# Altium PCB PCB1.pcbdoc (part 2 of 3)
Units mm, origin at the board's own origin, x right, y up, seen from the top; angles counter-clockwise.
Board outline 85.01 x 107.37 mm, 4 copper layers (Top Layer, Inner1, Inner2, Bottom Layer); 103 components, 145 nets, 660 pads, 277 vias.
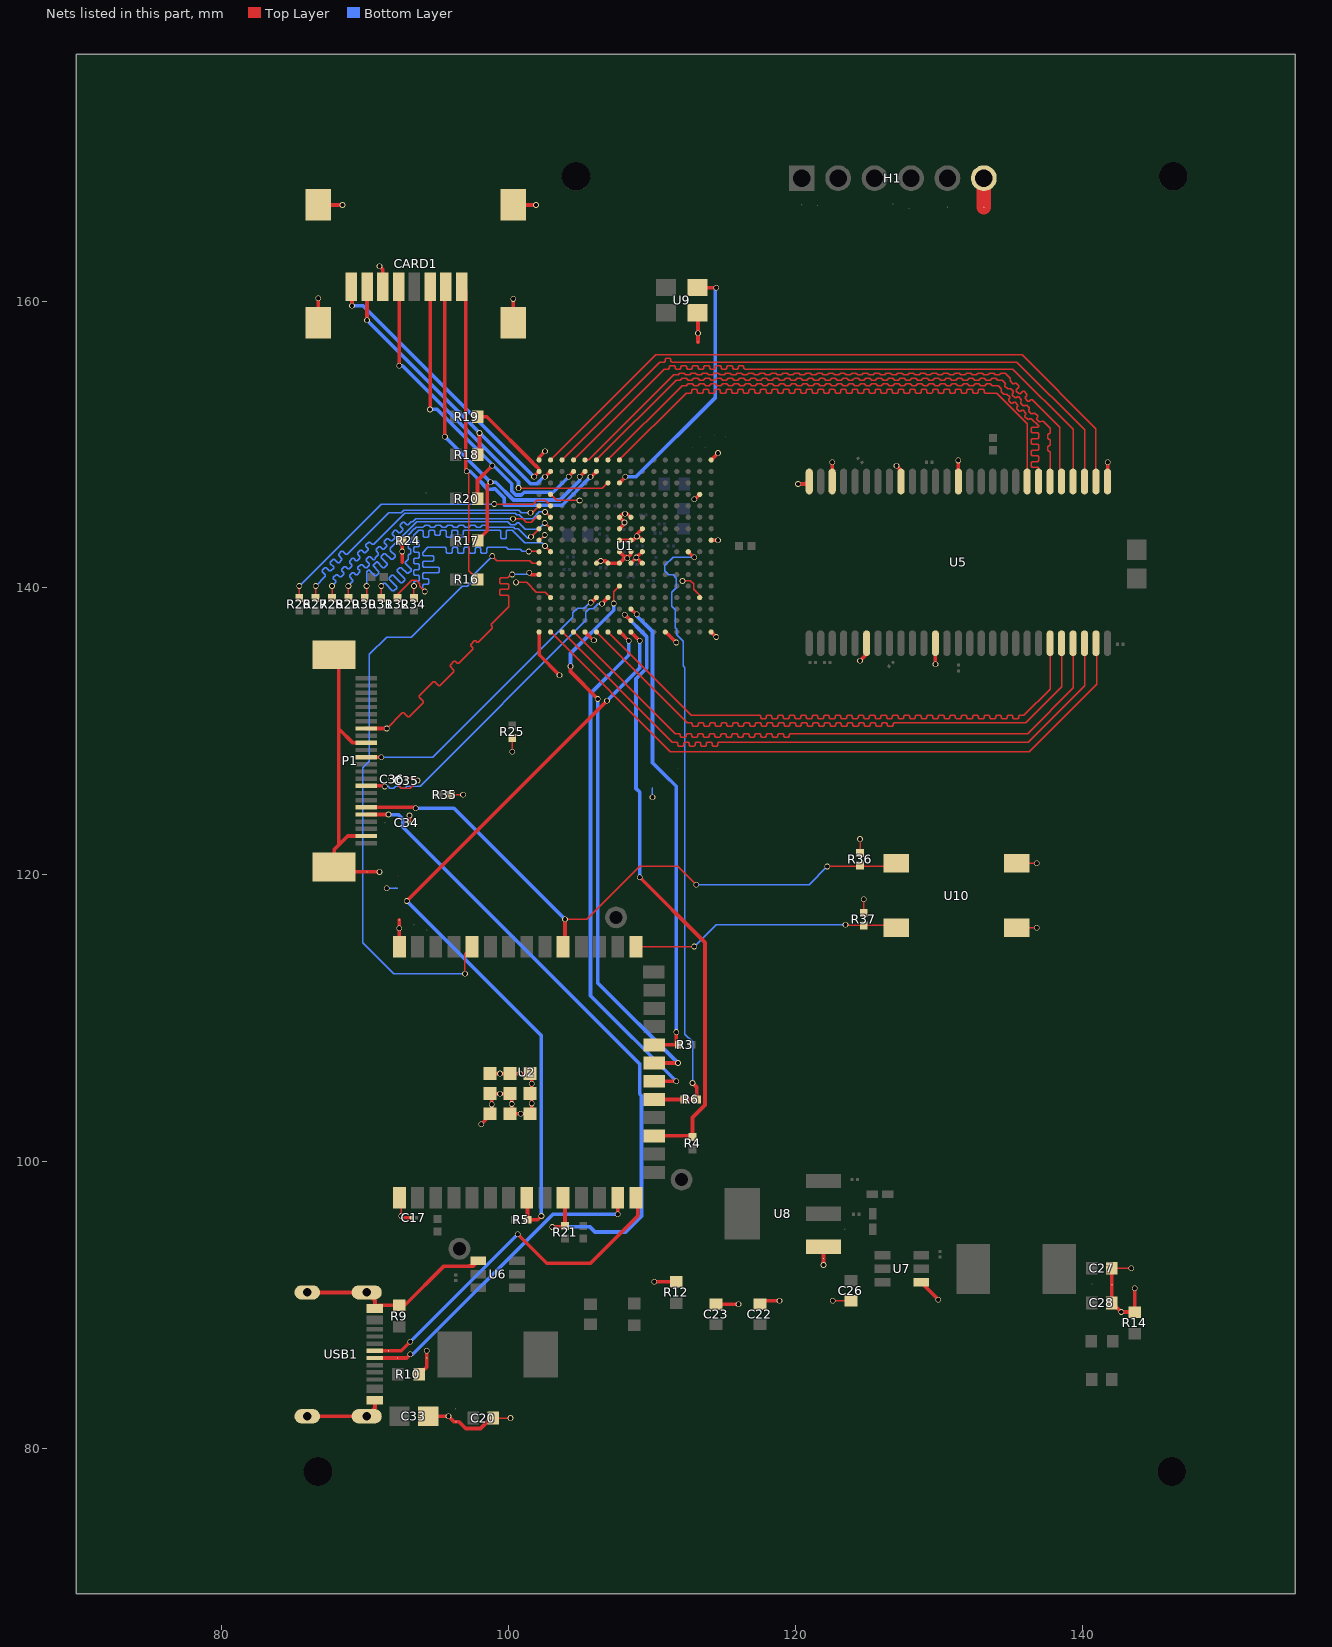
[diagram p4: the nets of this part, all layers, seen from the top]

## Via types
v1: diameter 0.4, hole 0.3, Top Layer to Bottom Layer, 261 vias
v2: diameter 0.61, hole 0.305, Top Layer to Bottom Layer, 16 vias

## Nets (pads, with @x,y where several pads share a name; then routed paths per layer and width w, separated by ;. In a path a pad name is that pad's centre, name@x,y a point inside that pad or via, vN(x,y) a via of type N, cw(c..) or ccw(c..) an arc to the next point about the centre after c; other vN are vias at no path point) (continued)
CCLK: R6.1 R6.2 U1.J14 U2.19 | length 44.3
  Top Layer w0.254: U2.19@110.292,104.318 R6.1@112.267,104.318 R6.2@113.133,104.318 113.133,105.155 v1(112.827,105.461) ; U1.J14@112.528,142.526 112.911,142.143 v1(112.954,142.143)
  Bottom Layer w0.1: v1(112.827,105.461) 112.827,108.34 112.296,108.871 112.296,134.44 112.171,134.565 112.171,136.277 111.714,136.734 111.714,137.124 111.615,137.223 111.615,138.479 111.386,138.708 111.386,139.707 111.705,140.026 111.705,140.68 111.47,140.915 111.184,140.915 110.899,141.199 110.899,141.567 111.475,142.143 v1(112.954,142.143)
CRYSTAL: U1.C8 U9.3 | length 18.2
  Top Layer w0.254: U1.C8@107.728,147.326 108.128,147.726 v1(108.128,147.752) ; U9.3@113.165,160.946 v1(114.478,160.946)
  Bottom Layer w0.254: v1(108.128,147.752) 108.89,147.752 114.425,153.287 114.425,160.893 v1(114.478,160.946)
D0: R26.1 U1.E2 | length 21
  Top Layer w0.1: R26.1@85.395,139.295 v1(85.395,140.132) ; v1@98.984,145.847 101.709,145.847 101.97,146.108 102.546,146.108 U1.E2@102.928,145.726
  Bottom Layer w0.1: v1(85.395,140.132) 91.11,145.847 v1(98.994,145.847)
D1: R27.1 U1.E1 | length 21.1
  Top Layer w0.1: R27.1@86.538,139.295 v1(86.538,140.132) ; v1(101.524,145.241) 101.643,145.241 U1.E1@102.128,145.726
  Bottom Layer w0.1: v1(86.538,140.132) 87.223,140.817 87.223,140.917 87.006,141.135 87.006,141.235 87.188,141.417 87.288,141.417 87.506,141.2 87.606,141.2 87.789,141.383 87.789,141.483 87.571,141.7 87.571,141.8 87.754,141.983 87.854,141.983 88.072,141.766 88.172,141.766 88.354,141.948 88.354,142.048 88.137,142.266 88.137,142.366 88.32,142.549 88.42,142.549 88.637,142.331 88.737,142.331 91.647,145.241 92.507,145.241 92.685,145.419 100.717,145.419 100.895,145.241 v1(101.524,145.241)
D2: R28.1 U1.F2 | length 21.5
  Top Layer w0.1: R28.1@87.681,139.295 v1(87.681,140.132) ; v1(102.537,145.296) 102.558,145.296 U1.F2@102.928,144.926
  Bottom Layer w0.1: v1(87.681,140.132) 87.935,140.386 87.935,140.486 87.781,140.64 87.781,140.74 87.964,140.923 88.064,140.923 88.218,140.769 88.318,140.769 88.501,140.952 88.501,141.052 88.347,141.206 88.347,141.306 88.53,141.489 88.63,141.489 88.784,141.335 88.884,141.335 89.066,141.517 89.066,141.617 88.912,141.771 88.912,141.871 89.095,142.054 89.195,142.054 89.349,141.9 89.449,141.9 89.632,142.083 89.632,142.183 89.478,142.337 89.478,142.437 89.661,142.62 89.761,142.62 89.915,142.466 90.015,142.466 90.198,142.649 90.198,142.749 90.044,142.903 90.044,143.003 90.227,143.186 90.327,143.186 90.481,143.032 90.581,143.032 92.768,145.219 100.465,145.219 100.575,145.11 100.743,145.11 101.014,144.839 101.691,144.839 102.147,145.296 v1(102.537,145.296)
D3: R29.1 U1.F1 | length 20.7
  Top Layer w0.1: R29.1@88.824,139.295 v1(88.824,140.132) ; v1(100.299,144.817) 100.998,144.817 101.23,144.585 101.564,144.585 101.922,144.943 102.111,144.943 U1.F1@102.128,144.926
  Bottom Layer w0.1: v1(88.824,140.132) 89.143,140.451 89.143,140.551 88.926,140.769 88.926,140.869 89.109,141.052 89.209,141.052 89.328,140.932 89.428,140.932 89.611,141.115 89.611,141.215 89.491,141.334 89.491,141.434 89.674,141.617 89.774,141.617 89.992,141.4 90.092,141.4 90.275,141.583 90.275,141.683 90.057,141.9 90.057,142 90.24,142.183 90.34,142.183 90.558,141.966 90.658,141.966 90.71,142.018 90.71,142.114 90.922,142.327 90.922,142.427 90.753,142.596 90.753,142.696 90.936,142.879 91.036,142.879 91.205,142.709 91.305,142.709 91.488,142.892 91.488,142.992 91.319,143.162 91.319,143.262 91.501,143.444 91.601,143.444 91.771,143.275 91.871,143.275 92.054,143.458 92.054,143.558 91.884,143.727 91.884,143.827 92.067,144.01 92.167,144.01 92.336,143.841 92.436,143.841 92.619,144.024 92.619,144.124 92.45,144.293 92.45,144.393 92.633,144.576 92.733,144.576 92.902,144.406 93.002,144.406 93.211,144.615 93.307,144.615 93.509,144.817 v1(100.299,144.817)
D4: R30.1 U1.G2 | length 21.3
  Top Layer w0.1: R30.1@89.967,139.295 90.094,139.422 v1(90.094,140.132) ; v1(102.522,144.529) 102.525,144.529 U1.G2@102.928,144.126
  Bottom Layer w0.1: v1(90.094,140.132) 90.094,141.119 90.24,141.265 90.258,141.265 90.67,140.853 90.77,140.853 90.953,141.036 90.953,141.136 90.541,141.548 90.541,141.566 90.806,141.831 90.824,141.831 91.236,141.419 91.336,141.419 91.519,141.602 91.519,141.702 91.107,142.114 91.107,142.214 91.29,142.397 91.39,142.397 91.802,141.985 91.902,141.985 92.084,142.168 92.084,142.268 91.745,142.607 91.745,142.77 92.171,143.196 92.271,143.196 92.489,142.978 92.589,142.978 92.772,143.16 92.772,143.26 92.554,143.479 92.554,143.579 93.592,144.617 99.93,144.617 100.132,144.415 100.465,144.415 100.592,144.542 100.701,144.542 101.153,144.09 102.082,144.09 v1(102.522,144.529)
D5: R31.1 U1.G1 | length 21
  Top Layer w0.1: R31.1@91.11,139.295 v1(91.11,140.132) ; v1(101.558,143.561) 101.563,143.561 U1.G1@102.128,144.126
  Bottom Layer w0.1: v1(91.11,140.132) 91.289,140.311 91.389,140.311 91.898,139.802 91.998,139.802 92.181,139.985 92.181,140.085 91.672,140.594 91.672,140.694 91.854,140.876 91.954,140.876 92.464,140.367 92.564,140.367 92.746,140.55 92.746,140.65 92.237,141.159 92.237,141.259 92.401,141.423 92.501,141.423 92.913,141.011 93.013,141.011 93.196,141.193 93.196,141.293 92.784,141.706 92.784,141.806 92.984,142.006 92.984,142.264 93.055,142.334 93.096,142.334 93.167,142.405 93.167,142.664 93.096,142.734 93.055,142.734 92.984,142.805 92.984,143.064 93.055,143.134 93.096,143.134 93.167,143.205 93.167,143.464 93.096,143.534 93.055,143.534 92.984,143.605 92.984,143.679 93.43,144.125 93.452,144.125 93.542,144.215 94.027,144.215 94.098,144.286 94.098,144.317 94.169,144.388 94.427,144.388 94.498,144.317 94.498,144.286 94.569,144.215 94.827,144.215 94.898,144.286 94.898,144.317 94.969,144.388 95.227,144.388 95.298,144.317 95.298,144.286 95.369,144.215 95.627,144.215 95.698,144.286 95.698,144.317 95.769,144.388 96.027,144.388 96.098,144.317 96.098,144.286 96.169,144.215 96.427,144.215 96.498,144.286 96.498,144.317 96.569,144.388 96.827,144.388 96.898,144.317 96.898,144.286 96.969,144.215 97.227,144.215 97.298,144.286 97.298,144.317 97.369,144.388 97.627,144.388 97.698,144.317 97.698,144.286 97.769,144.215 98.027,144.215 98.098,144.286 98.098,144.317 98.169,144.388 98.427,144.388 98.498,144.317 98.498,144.286 98.569,144.215 100.353,144.215 100.443,144.125 100.672,144.125 101.326,143.471 101.468,143.471 v1(101.558,143.561)
D6: R32.1 U1.J1 | length 20.9
  Top Layer w0.1: R32.1@92.253,139.295 92.253,139.558 93.229,140.534 93.563,140.534 93.798,140.299 93.798,140.111 v1(94.158,139.751) ; v1(101.397,142.545) 102.109,142.545 U1.J1@102.128,142.526
  Bottom Layer w0.1: v1(94.158,139.751) 94.01,139.899 94.01,140.183 94.081,140.254 94.345,140.254 94.416,140.324 94.416,140.583 94.345,140.654 94.081,140.654 94.01,140.724 94.01,140.983 94.081,141.054 95.103,141.054 95.174,141.124 95.174,141.383 95.103,141.454 94.081,141.454 94.01,141.524 94.01,141.783 94.081,141.854 94.722,141.854 94.793,141.924 94.793,142.183 94.722,142.254 94.081,142.254 94.01,142.324 94.01,142.458 94.372,142.82 95.59,142.82 95.661,142.749 95.661,142.489 95.731,142.418 95.99,142.418 96.061,142.489 96.061,142.749 96.131,142.82 96.39,142.82 96.461,142.749 96.461,142.489 96.531,142.418 96.79,142.418 96.861,142.489 96.861,142.749 96.931,142.82 97.19,142.82 97.261,142.749 97.261,142.489 97.331,142.418 97.59,142.418 97.661,142.489 97.661,142.749 97.731,142.82 97.99,142.82 98.061,142.749 98.061,142.489 98.131,142.418 98.39,142.418 98.461,142.489 98.461,142.749 98.531,142.82 99.852,142.82 99.979,142.693 100.802,142.693 100.95,142.545 v1(101.397,142.545)
D7: R34.1 U1.J2 | length 21
  Top Layer w0.1: R34.1@93.396,139.295 v1(93.396,140.132) ; v1(102.54,142.926) 102.54,142.914 U1.J2@102.928,142.526
  Bottom Layer w0.1: v1(93.396,140.132) 93.396,140.406 93.467,140.477 93.71,140.477 93.781,140.548 93.781,140.806 93.71,140.877 93.467,140.877 93.396,140.948 93.396,141.206 93.467,141.277 93.71,141.277 93.781,141.348 93.781,141.606 93.71,141.677 93.467,141.677 93.396,141.748 93.396,142.006 93.467,142.077 93.71,142.077 93.781,142.148 93.781,142.406 93.71,142.477 93.467,142.477 93.396,142.548 93.396,142.806 93.467,142.877 93.71,142.877 93.781,142.948 93.781,143.206 93.71,143.277 93.467,143.277 93.396,143.348 93.396,143.688 93.723,144.015 93.972,144.015 94.042,143.944 94.042,143.606 94.113,143.535 94.372,143.535 94.442,143.606 94.442,143.944 94.513,144.015 94.772,144.015 94.842,143.944 94.842,143.747 94.913,143.677 95.172,143.677 95.242,143.747 95.242,143.944 95.313,144.015 95.572,144.015 95.642,143.944 95.642,143.606 95.713,143.535 95.972,143.535 96.042,143.606 96.042,143.944 96.113,144.015 96.372,144.015 96.442,143.944 96.442,143.606 96.513,143.535 96.772,143.535 96.842,143.606 96.842,143.944 96.913,144.015 99.367,144.015 99.437,143.944 99.437,143.505 99.508,143.434 99.767,143.434 99.837,143.505 99.837,143.944 99.908,144.015 100.271,144.015 101.127,143.159 102.307,143.159 v1(102.54,142.926)
DIN: U1.T8 U2.20 | length 36.6
  Top Layer w0.254: U1.T8@107.728,136.926 107.778,136.926 v1(108.382,136.322) ; U2.20@110.292,105.588 v1(111.684,105.588)
  Bottom Layer w0.254: v1(108.382,136.322) 108.382,135.306 105.715,132.639 105.715,111.557 v1(111.684,105.588)
DN: pad.55@92.253,86.284 U2.13 USB1.A7 | length 22.3
  Top Layer w0.254: USB1.A7@90.678,86.288 91.975,86.288 92.892,86.288 v1(93.142,86.538) ; v1(107.62,96.317) 107.62,97.351 U2.13@107.742,97.473
  Bottom Layer w0.254: v1(93.142,86.538) 93.311,86.538 103.09,96.317 v1(107.62,96.317)
DONE: pad.55@110.865,126.981 R3.2 U1.P9 U2.22 | length 33.4
  Top Layer w0.254: U1.P9@108.528,138.526 108.898,138.156 v1(108.946,138.156) ; U2.22@110.292,108.128 R3.2@111.886,108.128 111.684,108.33 v1(111.684,109.017)
  Bottom Layer w0.254: v1(108.946,138.156) 108.946,138.044 110.033,136.957 110.033,127.813 pad.55@110.865,126.981 111.684,126.162 v1(111.684,109.017)
DOUT: U1.M8 U2.21 | length 39.3
  Top Layer w0.1: v1(107.328,138.911) 107.328,139.726 U1.M8@107.728,140.126
  Top Layer w0.254: v1(104.318,134.544) 104.318,134.163 v1(106.223,132.258) ; U2.21@110.292,106.858 v1(111.811,106.858)
  Bottom Layer w0.254: v1(104.318,134.544) 104.318,135.433 107.328,138.443 v1(107.328,138.911) ; v1(106.223,132.258) 106.223,112.446 v1(111.811,106.858)
DP: pad.55@91.618,86.792 U2.14 USB1.A6 | length 25.2
  Top Layer w0.254: USB1.A6@90.678,86.788 91.93,86.788 92.503,86.788 v1(93.142,87.427) ; v1(100.635,94.92) 102.667,92.888 105.715,92.888 109.012,96.185 U2.14@109.012,97.473
  Bottom Layer w0.254: v1(93.142,87.427) v1(100.635,94.92)
GND: C17.1 C20.1 C22.1 C23.1 C26.1 C27.1 C28.1 C33.1 C34.2 C35.2 C36.2 CARD1.6 CARD1.9 CARD1.10 CARD1.11 CARD1.12 H1.6 P1.2 P1.15 P1.25 P1.26 pad.55@90.131,120.193 pad.55@92.126,119.05 pad.55@92.375,116.832 pad.55@94.285,86.284 pad.55@96.317,81.839 pad.55@110.033,126.035 pad.55@113.208,157.15 pad.55@121.965,93.234 pad.55@133.147,166.548 pad.55@142.081,91.393 R9.1 R10.1 R12.1 R14.1 R24.1 R25.1 R35.2 R36.2 R37.2 U1.A1 U1.A16 U1.D2 U1.D15 U1.F8 U1.F9 U1.G8 U1.G10 U1.H1 U1.H8 U1.H9 U1.H10 U1.H16 U1.J8 U1.J9 U1.J10 U1.K6 U1.K7 U1.K8 U1.K9 U1.K10 U1.N2 U1.N15 U1.T1 U1.T5 U1.T12 U1.T16 U2.1 U2.40 U2.41 U5.6 U5.12 U5.28 U5.41 U5.46 U5.52 U5.54 U6.4 U7.4 U8.1 U9.2 U10.2 U10.4 USB1.1 USB1.2 USB1.3 USB1.4 USB1.A1B12 USB1.B1A12 | length 143
  Top Layer w0.1: C36.2@92.067,126.67 92.067,126.475 92.501,126.041 93.148,126.041 93.65,126.543 v1(93.65,126.564) 93.476,126.738 C35.2@92.888,126.738 ; U2.1@92.375,97.473 92.502,97.346 v1(92.502,96.19) ; R35.2@95.974,125.576 v1(96.825,125.576) ; C20.1@98.922,82.093 v1(100.127,82.093) ; v1(100.254,128.575) R25.1@100.254,129.539 ; v1(100.508,140.386) 101.27,140.386 101.942,139.714 102.54,139.714 U1.N2@102.928,139.326 ; 102.286,143.434 102.528,143.676 v1(102.528,143.688) ; U1.D2@102.928,146.526 103.353,146.101 103.563,146.101 103.57,146.108 104.686,146.108 104.693,146.101 v1@104.953,146.101 ; v1(112.128,140.478) 112.267,140.478 112.297,140.508 112.686,140.508 112.91,140.284 112.91,139.895 113.328,139.477 U1.N15@113.328,139.326 ; v1(122.606,90.283) C26.1@123.876,90.283 ; R36.2@124.511,121.515 v1(124.511,122.479) ; R37.2@124.765,117.324 v1(124.765,118.288) ; U10.4@135.442,116.292 v1(136.83,116.292) ; U10.2@135.442,120.792 v1(136.83,120.792) ; C27.1@142.081,92.546 v1(143.434,92.546)
  Top Layer w0.254: USB1.4@85.954,82.218 USB1.2@90.103,82.218 90.678,82.793 USB1.B1A12@90.678,83.338 ; USB1.3@85.954,90.858 USB1.1@90.103,90.858 90.678,90.283 USB1.A1B12@90.678,89.738 90.899,89.958 R9.1@92.38,89.958 92.761,89.958 95.498,92.695 97.212,92.695 97.222,92.705 97.517,92.705 U6.4@97.888,93.076 ; CARD1.10@86.723,158.511 v1(86.723,160.202) ; CARD1.9@86.723,166.711 v1(88.408,166.711) ; P1.25@87.819,135.341 88.153,135.007 88.153,130.184 ; P1.2@90.08,122.695 88.786,122.695 88.153,122.062 ; P1.15@90.081,129.191 89.147,129.191 88.153,130.184 ; v1(90.996,162.438) 91.223,162.211 CARD1.6@91.223,161.011 ; v1(91.001,120.193) pad.55@90.131,120.193 88.172,120.193 P1.26@87.826,120.539 87.826,121.735 88.153,122.062 ; pad.55@92.375,116.832 v1(92.375,116.26) 92.375,115.1 U2.40@92.502,114.973 ; v1(92.502,96.19) 92.629,96.063 C17.1@93.201,96.063 ; 92.582,141.783 v1(92.582,142.539) R24.1@92.582,143.307 ; C34.2@93.083,123.622 v1(93.083,124.13) ; R10.1@93.768,85.141 94.285,85.658 pad.55@94.285,86.284 v1(94.285,86.792) ; C33.1@94.396,82.22 v1(95.809,82.22) 96.19,81.839 96.531,81.839 97.006,81.364 98.038,81.364 98.767,82.093 C20.1@98.922,82.093 ; v1(98.096,102.597) 98.822,103.323 v1(98.822,103.976) 98.822,104.723 v1(99.398,104.723) 100.222,104.723 v1(100.222,104.001) 100.222,103.323 v1(100.842,103.323) 101.622,103.323 v1(101.622,104.045) v1(101.622,105.407) 101.622,106.123 v1(100.773,106.123) v1(99.398,106.123) U2.41@98.822,106.123 ; CARD1.11@100.323,158.511 v1(100.323,160.16) ; CARD1.12@100.323,166.711 v1(101.905,166.711) ; U1.T1@102.128,136.926 102.128,135.337 v1(103.556,133.909) ; U1.A1@102.128,148.926 102.128,149.118 v1(102.54,149.53) ; U1.T5@105.328,136.926 105.911,136.343 v1(105.948,136.343) ; U1.K6@106.128,141.726 106.282,141.881 v1(106.427,141.881) 106.774,141.881 U1.K7@106.928,141.726 U1.K8@107.728,141.726 v1@108.19,142.188 ; U1.J8@107.728,142.526 108.066,142.188 v1@108.19,142.188 ; U1.H8@107.728,143.326 U1.H9@108.528,143.326 108.679,143.326 v1(108.947,143.594) ; U1.G8@107.728,144.126 108.08,144.478 v1(108.08,144.557) 108.08,144.574 U1.F8@107.728,144.926 107.982,145.18 v1(108.119,145.18) 108.274,145.18 U1.F9@108.528,144.926 ; U1.K9@108.528,141.726 108.907,142.105 v1(108.907,142.118) ; U1.J9@108.528,142.526 108.528,142.329 v1(108.269,142.069) 108.269,142.109 v1@108.19,142.188 ; U1.K10@109.172,141.754 109.172,141.852 v1(108.907,142.118) ; U1.J10@109.328,142.526 109.315,142.526 v1(108.907,142.118) ; U1.H10@109.328,143.326 109.06,143.594 v1(108.947,143.594) ; U1.G10@109.328,144.126 108.947,143.745 v1(108.947,143.594) ; v1(110.16,91.609) R12.1@111.684,91.609 ; U1.T12@110.928,136.926 110.953,136.926 v1(111.685,136.194) ; v1@112.954,146.228 113.03,146.228 U1.D15@113.328,146.526 ; U9.2@113.165,159.196 113.208,159.153 v1(113.208,157.755) pad.55@113.208,157.15 ; U1.T16@114.128,136.926 v1(114.478,136.576) ; U1.H16@114.128,143.326 v1(114.605,143.328) ; U1.A16@114.128,148.926 v1(114.605,149.403) ; C23.1@114.478,90.032 v1(116.032,90.032) ; C22.1@117.526,90.032 117.777,90.283 v1(118.897,90.283) ; v1(120.193,147.244) 120.661,147.244 U5.54@120.969,147.552 ; v1(121.965,92.771) pad.55@121.965,93.234 U8.1@121.965,94.046 ; U5.52@122.569,147.552 v1(122.569,148.768) ; v1(124.511,134.925) 124.969,135.383 U5.6@124.969,136.141 ; v1(127.051,148.514) 127.369,148.196 U5.46@127.369,147.425 ; U7.4@128.782,91.557 129.972,90.367 v1(129.972,90.348) ; v1(129.769,134.671) U5.12@129.769,136.141 ; U5.41@131.369,147.552 v1(131.369,148.895) ; U5.28@141.769,147.425 141.783,147.439 v1(141.783,148.768) ; C27.1@142.081,92.546 pad.55@142.081,91.393 C28.1@142.081,90.133 v1(142.725,89.489) R14.1@143.667,89.489 v1(143.667,91.149) ; 88.153,122.062 88.153,130.184
  Top Layer w1: pad.55@133.147,166.548 H1.6@133.147,168.58
  Bottom Layer w0.1: v1(91.491,119.05) 92.253,119.05 ; v1(110.033,125.4) pad.55@110.033,126.035
  other v1: 104.952,146.102 112.954,146.181
HREF: P1.9 U1.N7 | length 22.9
  Top Layer w0.254: P1.9@90.08,126.194 91.323,126.194 v1(91.365,126.152) ; v1@106.477,138.862 106.477,138.875 U1.N7@106.928,139.326
  Bottom Layer w0.1: v1(91.365,126.152) 91.594,126.152 91.712,126.035 91.985,126.035 92.112,126.162 92.385,126.162 92.512,126.035 92.785,126.035 92.912,126.162 93.826,126.162 105.394,137.73 105.394,138.313 105.629,138.548 105.909,138.548 106.257,138.896 v1(106.511,138.896)
INITN: pad.55@93.673,117.376 R5.1 U1.T9 U2.8 | length 54.3
  Top Layer w0.254: v1(92.888,118.161) v1(106.858,132.131) ; U2.8@101.392,97.473 101.322,97.403 R5.1@101.322,95.936 102.032,95.936 v1(102.286,96.19) ; U1.T9@108.528,136.926 109.132,136.322 v1(109.144,136.322)
  Bottom Layer w0.254: v1(92.888,118.161) pad.55@93.673,117.376 102.286,108.763 v1(102.286,96.19) ; v1(106.858,132.131) 109.144,134.417 v1(109.144,136.322)
M_CLK: CARD1.5 U1.C7 | length 24
  Top Layer w0.1: v1(100.69,146.962) 100.707,146.944 106.546,146.944 U1.C7@106.928,147.326
  Top Layer w0.254: CARD1.5@92.323,161.011 92.38,160.954 v1(92.38,155.499)
  Bottom Layer w0.254: v1(92.38,155.499) 92.592,155.499 100.69,147.401 v1(100.69,146.962)
M_CMD: CARD1.3 R20.1 U1.B4 | length 24.7
  Top Layer w0.254: v1(94.523,152.451) CARD1.3@94.523,161.011 ; R20.1@97.832,146.228 97.832,147.489 v1(98.857,148.514) ; v1(104.191,147.752) 104.191,147.789 U1.B4@104.528,148.126
  Bottom Layer w0.254: v1(94.523,152.451) 95.031,152.451 100.211,147.271 100.211,146.763 100.491,146.483 100.888,146.483 101.087,146.682 103.121,146.682 v1(104.191,147.752)
M_D0: CARD1.7 R18.1 U1.B2 | length 21.8
  Top Layer w0.254: v1(90.123,158.674) CARD1.7@90.123,161.011 ; R18.1@97.832,149.276 97.968,149.412 v1(97.968,150.8) ; v1(102.54,147.752) 102.554,147.752 U1.B2@102.928,148.126
  Bottom Layer w0.254: v1(90.123,158.674) 101.524,147.273 101.976,147.273 102.455,147.752 v1(102.54,147.752)
M_D1: CARD1.8 R19.1 U1.B1 | length 25.5
  Top Layer w0.254: CARD1.8@89.023,161.011 89.078,160.956 v1(89.078,159.69) ; R19.1@97.832,151.943 98.467,151.943 101.669,148.741 101.669,148.736 101.938,148.467 101.943,148.467 102.096,148.315 U1.B1@102.096,148.093 ; v1(101.778,147.752) 101.778,147.776 U1.B1@102.096,148.093 ; U1.B1@102.128,148.126 U1.B1@102.096,148.093
  Bottom Layer w0.254: v1(89.078,159.69) 89.84,159.69 v1(101.778,147.752)
M_D2: CARD1.1 R16.1 U1.B6 | length 32.2
  Top Layer w0.1: v1(97.079,148.133) 97.227,147.985 97.227,141.19 R16.1@97.828,140.589
  Top Layer w0.254: CARD1.1@96.723,161.011 97.008,160.726 97.008,148.204 v1(97.079,148.133) ; v1(105.715,147.752) 105.754,147.752 U1.B6@106.128,148.126
  Bottom Layer w0.254: v1(97.079,148.133) 97.333,148.133 98.251,147.215 98.251,147.173 98.532,146.892 98.928,146.892 98.942,146.906 99.067,146.906 99.704,146.269 99.704,145.775 103.738,145.775 v1(105.715,147.752)
M_D3: CARD1.2 R17.1 U1.B5 | length 27.5
  Top Layer w0.254: v1(95.555,150.546) 95.555,160.943 CARD1.2@95.623,161.011 ; R17.1@97.832,143.307 98.515,143.989 98.515,147.156 v1(98.73,147.371) ; v1(104.953,147.752) U1.B5@105.328,148.126
  Bottom Layer w0.254: v1(95.555,150.546) v1(98.73,147.371) 99.102,147.371 100.345,146.129 103.591,146.129 104.953,147.491 v1(104.953,147.752)
MCLK: P1.13 U1.N6 | length 20.8
  Top Layer w0.254: P1.13@90.08,128.194 v1(91.11,128.194) ; v1@105.715,138.989 105.791,138.989 U1.N6@106.128,139.326
  Bottom Layer w0.1: v1(91.11,128.194) 94.717,128.194 104.482,137.96 104.482,138.264 104.805,138.587 105.276,138.587 105.664,138.975 v1(105.729,138.975)
PCLK: P1.17 U1.L1 | length 22.6
  Top Layer w0.1: v1(91.491,130.194) 92.586,131.29 92.686,131.29 92.956,131.02 93.056,131.02 94.034,131.997 94.034,132.097 93.764,132.367 93.764,132.467 94.742,133.445 94.842,133.445 95.112,133.175 95.212,133.175 96.189,134.153 96.189,134.253 95.919,134.522 95.919,134.622 96.17,134.874 96.27,134.874 96.409,134.736 96.509,134.736 97.486,135.713 97.486,135.813 97.348,135.951 97.348,136.051 97.601,136.304 97.701,136.304 97.781,136.224 97.881,136.224 98.858,137.202 98.858,137.302 98.779,137.382 98.779,137.482 100,138.703 100,139.422 99.929,139.492 99.441,139.492 99.37,139.563 99.37,139.822 99.441,139.892 99.929,139.892 100,139.963 100,140.222 99.929,140.292 99.441,140.292 99.37,140.363 99.37,140.622 99.441,140.692 99.929,140.692 100.175,140.938 v1(100.254,140.938)
  Top Layer w0.254: P1.17@90.079,130.194 v1(91.491,130.194) ; v1(101.442,141.066) 101.581,140.926 U1.L1@102.128,140.926
  Bottom Layer w0.1: v1(100.254,140.938) 101.314,140.938 v1(101.442,141.066)
PROGRAM: R37.1 U2.27 U10.3 | length 18.9
  Top Layer w0.1: U2.27@108.885,114.973 112.941,114.973 v1(112.954,114.986) ; v1(123.495,116.51) 123.547,116.458 R37.1@124.765,116.458 126.876,116.458 U10.3@127.042,116.292
  Bottom Layer w0.1: v1(112.954,114.986) 114.478,116.51 v1(123.495,116.51)
PROGRAMN: pad.55@108.89,126.014 R4.2 U1.R9 U2.17 | length 42.9
  Top Layer w0.254: v1(108.091,138.137) 108.117,138.137 U1.R9@108.528,137.726 ; v1(109.144,119.812) 113.695,115.261 113.695,103.932 112.827,103.065 R4.2@112.827,101.703 112.752,101.778 U2.17@110.292,101.778
  Bottom Layer w0.254: v1(108.091,138.137) 109.623,136.605 109.623,134.395 108.89,133.662 pad.55@108.89,126.014 109.144,125.76 v1(109.144,119.812)
RESET: P1.6 pad.55@99.749,121.074 R36.1 U2.31 U10.1 | length 44.8
  Top Layer w0.1: v1(103.932,116.891) 105.461,116.891 109.144,120.574 111.811,120.574 v1(113.081,119.304) ; v1(122.225,120.574) 126.824,120.574 U10.1@127.042,120.792
  Top Layer w0.254: P1.6@90.08,124.695 93.466,124.695 v1(93.523,124.638) ; U2.31@103.932,114.973 v1(103.932,116.891)
  Bottom Layer w0.1: v1(113.081,119.304) 120.955,119.304 v1(122.225,120.574)
  Bottom Layer w0.254: v1(93.523,124.638) 96.185,124.638 pad.55@99.749,121.074 v1(103.932,116.891)
RX: U1.K1 U2.36 | length 45.5
  Top Layer w0.1: v1(96.952,113.081) 96.952,114.47 U2.36@97.455,114.973 ; v1(98.858,142.219) 99.186,141.891 101.485,141.891 101.65,141.726 U1.K1@102.128,141.726
  Bottom Layer w0.1: v1(96.952,113.081) 91.999,113.081 89.84,115.24 89.84,127.468 90.28,127.908 90.28,135.365 91.491,136.576 93.215,136.576 96.75,140.111 97.119,140.111 97.354,140.346 97.354,140.715 v1(98.858,142.219)
SCL: P1.5 R21.1 U2.10 | length 46.9
  Top Layer w0.254: P1.5@90.08,124.194 v1(91.618,124.194) ; v1(103.048,95.428) 103.885,95.428 R21.1@103.937,95.48 ; U2.10@103.932,97.473 103.937,97.468 R21.1@103.937,95.555
  Bottom Layer w0.254: v1(91.618,124.194) 91.745,124.194 91.766,124.174 92.324,124.174 92.605,123.893 92.605,123.334 109.144,106.795 109.144,104.706 109.271,104.579 109.271,96.19 108.157,95.076 106.025,95.076 105.673,95.428 v1(103.048,95.428)
SD_A0: U1.T6 U5.23 | length 45.3
  Top Layer w0.1: U1.T6@106.128,136.926 112.447,130.607 112.747,130.607 112.818,130.536 112.818,130.424 112.888,130.353 113.147,130.353 113.218,130.424 113.218,130.536 113.288,130.607 113.547,130.607 113.618,130.536 113.618,130.424 113.688,130.353 113.947,130.353 114.018,130.424 114.018,130.536 114.088,130.607 114.347,130.607 114.418,130.536 114.418,130.424 114.488,130.353 114.747,130.353 114.818,130.424 114.818,130.536 114.888,130.607 115.147,130.607 115.218,130.536 115.218,130.424 115.288,130.353 115.547,130.353 115.618,130.424 115.618,130.536 115.688,130.607 115.947,130.607 116.018,130.536 116.018,130.424 116.088,130.353 116.347,130.353 116.418,130.424 116.418,130.536 116.488,130.607 116.747,130.607 116.818,130.536 116.818,130.424 116.888,130.353 117.147,130.353 117.218,130.424 117.218,130.536 117.288,130.607 117.547,130.607 117.618,130.536 117.618,130.424 117.688,130.353 117.947,130.353 118.018,130.424 118.018,130.536 118.088,130.607 118.347,130.607 118.418,130.536 118.418,130.424 118.488,130.353 118.747,130.353 118.818,130.424 118.818,130.536 118.888,130.607 119.147,130.607 119.218,130.536 119.218,130.424 119.288,130.353 119.547,130.353 119.618,130.424 119.618,130.536 119.688,130.607 119.947,130.607 120.018,130.536 120.018,130.424 120.088,130.353 120.347,130.353 120.418,130.424 120.418,130.536 120.488,130.607 120.747,130.607 120.818,130.536 120.818,130.424 120.888,130.353 121.147,130.353 121.218,130.424 121.218,130.536 121.288,130.607 121.547,130.607 121.618,130.536 121.618,130.424 121.688,130.353 121.947,130.353 122.018,130.424 122.018,130.536 122.088,130.607 122.347,130.607 122.418,130.536 122.418,130.424 122.488,130.353 122.747,130.353 122.818,130.424 122.818,130.536 122.888,130.607 123.147,130.607 123.218,130.536 123.218,130.424 123.288,130.353 123.547,130.353 123.618,130.424 123.618,130.536 123.688,130.607 123.947,130.607 124.018,130.536 124.018,130.424 124.088,130.353 124.347,130.353 124.418,130.424 124.418,130.536 124.488,130.607 124.747,130.607 124.818,130.536 124.818,130.424 124.888,130.353 125.147,130.353 125.218,130.424 125.218,130.536 125.288,130.607 125.547,130.607 125.618,130.536 125.618,130.424 125.688,130.353 125.947,130.353 126.018,130.424 126.018,130.536 126.088,130.607 126.347,130.607 126.418,130.536 126.418,130.424 126.488,130.353 126.747,130.353 126.818,130.424 126.818,130.536 126.888,130.607 136.068,130.607 138.569,133.108 U5.23@138.569,136.141
SD_A1: U1.T4 U5.24 | length 45.6
  Top Layer w0.1: U1.T4@104.528,136.926 111.609,129.845 111.909,129.845 111.98,129.774 111.98,129.662 112.05,129.591 112.309,129.591 112.38,129.662 112.38,129.774 112.45,129.845 112.709,129.845 112.78,129.774 112.78,129.662 112.85,129.591 113.109,129.591 113.18,129.662 113.18,129.774 113.25,129.845 113.509,129.845 113.58,129.774 113.58,129.662 113.65,129.591 113.909,129.591 113.98,129.662 113.98,129.774 114.05,129.845 114.309,129.845 114.38,129.774 114.38,129.662 114.45,129.591 114.709,129.591 114.78,129.662 114.78,129.774 114.85,129.845 115.109,129.845 115.18,129.774 115.18,129.662 115.25,129.591 115.509,129.591 115.58,129.662 115.58,129.774 115.65,129.845 115.909,129.845 115.98,129.774 115.98,129.662 116.05,129.591 116.309,129.591 116.38,129.662 116.38,129.774 116.45,129.845 116.709,129.845 116.78,129.774 116.78,129.662 116.85,129.591 117.109,129.591 117.18,129.662 117.18,129.774 117.25,129.845 117.509,129.845 117.58,129.774 117.58,129.662 117.65,129.591 117.909,129.591 117.98,129.662 117.98,129.774 118.05,129.845 118.309,129.845 118.38,129.774 118.38,129.662 118.45,129.591 118.709,129.591 118.78,129.662 118.78,129.774 118.85,129.845 119.109,129.845 119.18,129.774 119.18,129.662 119.25,129.591 119.509,129.591 119.58,129.662 119.58,129.774 119.65,129.845 136.195,129.845 139.37,133.02 U5.24@139.37,136.14
SD_A2: U1.T3 U5.25 | length 45.9
  Top Layer w0.1: U1.T3@103.728,136.926 111.407,129.247 111.73,129.247 111.801,129.176 111.801,129.027 111.871,128.956 112.13,128.956 112.201,129.027 112.201,129.176 112.271,129.247 112.53,129.247 112.601,129.176 112.601,129.027 112.671,128.956 112.93,128.956 113.001,129.027 113.001,129.176 113.071,129.247 113.33,129.247 113.401,129.176 113.401,129.027 113.471,128.956 113.73,128.956 113.801,129.027 113.801,129.176 113.871,129.247 114.13,129.247 114.201,129.176 114.201,129.027 114.271,128.956 114.53,128.956 114.601,129.027 114.601,129.176 114.671,129.247 136.232,129.247 140.169,133.184 U5.25@140.169,136.141
SD_A3: U1.T2 U5.26 | length 46.4
  Top Layer w0.1: U1.T2@102.928,136.926 111.279,128.575 136.322,128.575 141.021,133.274 141.021,136.089 U5.26@140.969,136.141
SD_A4: U1.A2 U5.29 | length 46.9
  Top Layer w0.1: U1.A2@102.928,148.926 110.263,156.261 135.814,156.261 140.969,151.106 U5.29@140.969,147.425
SD_A5: U1.A3 U5.30 | length 45.2
  Top Layer w0.1: U1.A3@103.728,148.926 110.555,155.753 110.855,155.753 110.926,155.824 110.926,155.936 110.996,156.007 111.255,156.007 111.326,155.936 111.326,155.824 111.396,155.753 135.433,155.753 140.169,151.017 U5.30@140.169,147.425
SD_A6: U1.A4 U5.31 | length 45.2
  Top Layer w0.1: U1.A4@104.528,148.926 110.847,155.245 111.147,155.245 111.218,155.316 111.218,155.428 111.288,155.499 111.547,155.499 111.618,155.428 111.618,155.316 111.688,155.245 111.947,155.245 112.018,155.316 112.018,155.428 112.088,155.499 112.347,155.499 112.418,155.428 112.418,155.316 112.488,155.245 112.747,155.245 112.818,155.316 112.818,155.428 112.888,155.499 113.147,155.499 113.218,155.428 113.218,155.316 113.288,155.245 113.547,155.245 113.618,155.316 113.618,155.428 113.688,155.499 113.947,155.499 114.018,155.428 114.018,155.316 114.088,155.245 114.347,155.245 114.418,155.316 114.418,155.428 114.488,155.499 114.747,155.499 114.818,155.428 114.818,155.316 114.888,155.245 115.147,155.245 115.218,155.316 115.218,155.428 115.288,155.499 115.547,155.499 115.618,155.428 115.618,155.316 115.688,155.245 115.947,155.245 116.018,155.316 116.018,155.428 116.088,155.499 116.347,155.499 116.418,155.428 116.418,155.316 116.488,155.245 135.179,155.245 139.369,151.055 U5.31@139.369,147.425
SD_A7: U1.A5 U5.32 | length 45.1
  Top Layer w0.1: U1.A5@105.328,148.926 105.588,148.926 111.526,154.864 111.826,154.864 111.953,154.991 112.226,154.991 112.353,154.864 112.626,154.864 112.753,154.991 113.026,154.991 113.153,154.864 113.426,154.864 113.553,154.991 113.826,154.991 113.953,154.864 114.226,154.864 114.353,154.991 114.626,154.991 114.753,154.864 115.026,154.864 115.153,154.991 115.426,154.991 115.553,154.864 115.826,154.864 115.953,154.991 116.226,154.991 116.353,154.864 116.626,154.864 116.753,154.991 117.026,154.991 117.153,154.864 117.426,154.864 117.553,154.991 117.826,154.991 117.953,154.864 118.226,154.864 118.353,154.991 118.626,154.991 118.753,154.864 119.026,154.864 119.153,154.991 119.426,154.991 119.553,154.864 119.826,154.864 119.953,154.991 120.226,154.991 120.353,154.864 120.626,154.864 120.753,154.991 121.026,154.991 121.153,154.864 121.426,154.864 121.553,154.991 121.826,154.991 121.953,154.864 122.226,154.864 122.353,154.991 122.626,154.991 122.753,154.864 123.026,154.864 123.153,154.991 123.426,154.991 123.553,154.864 123.826,154.864 123.953,154.991 124.226,154.991 124.353,154.864 124.626,154.864 124.753,154.991 125.026,154.991 125.153,154.864 125.426,154.864 125.553,154.991 125.826,154.991 125.953,154.864 126.226,154.864 126.353,154.991 126.626,154.991 126.753,154.864 127.026,154.864 127.153,154.991 127.426,154.991 127.553,154.864 127.826,154.864 127.953,154.991 128.226,154.991 128.353,154.864 128.626,154.864 128.753,154.991 129.026,154.991 129.153,154.864 129.426,154.864 129.553,154.991 129.826,154.991 129.953,154.864 130.226,154.864 130.353,154.991 130.626,154.991 130.753,154.864 131.026,154.864 131.153,154.991 131.426,154.991 131.553,154.864 131.826,154.864 131.953,154.991 132.226,154.991 132.353,154.864 132.626,154.864 132.753,154.991 133.026,154.991 133.153,154.864 133.426,154.864 133.553,154.991 133.826,154.991 133.953,154.864 134.226,154.864 134.353,154.991 134.626,154.991 134.998,154.619 134.998,154.44 135.181,154.257 135.281,154.257 135.293,154.269 135.393,154.269 135.576,154.086 135.576,153.986 135.422,153.832 135.422,153.732 135.604,153.549 135.704,153.549 135.859,153.703 135.959,153.703 136.142,153.52 136.142,153.42 136.036,153.315 136.036,153.215 136.219,153.032 136.319,153.032 136.424,153.138 136.524,153.138 138.442,151.22 138.442,147.552 U5.32@138.569,147.425
SD_A8: U1.A6 U5.33 | length 44.4
  Top Layer w0.1: U1.A6@106.128,148.926 111.685,154.483 111.985,154.483 112.056,154.554 112.056,154.564 112.126,154.635 112.385,154.635 112.456,154.564 112.456,154.554 112.526,154.483 112.785,154.483 112.856,154.554 112.856,154.564 112.926,154.635 113.185,154.635 113.256,154.564 113.256,154.554 113.326,154.483 113.585,154.483 113.656,154.554 113.656,154.564 113.726,154.635 113.985,154.635 114.056,154.564 114.056,154.554 114.126,154.483 114.385,154.483 114.456,154.554 114.456,154.564 114.526,154.635 114.785,154.635 114.856,154.564 114.856,154.554 114.926,154.483 115.185,154.483 115.256,154.554 115.256,154.564 115.326,154.635 115.585,154.635 115.656,154.564 115.656,154.554 115.726,154.483 115.985,154.483 116.056,154.554 116.056,154.564 116.126,154.635 116.385,154.635 116.456,154.564 116.456,154.554 116.526,154.483 116.785,154.483 116.856,154.554 116.856,154.564 116.926,154.635 117.185,154.635 117.256,154.564 117.256,154.554 117.326,154.483 117.585,154.483 117.656,154.554 117.656,154.564 117.726,154.635 117.985,154.635 118.056,154.564 118.056,154.554 118.126,154.483 118.385,154.483 118.456,154.554 118.456,154.564 118.526,154.635 118.785,154.635 118.856,154.564 118.856,154.554 118.926,154.483 119.185,154.483 119.256,154.554 119.256,154.564 119.326,154.635 119.585,154.635 119.656,154.564 119.656,154.554 119.726,154.483 119.985,154.483 120.056,154.554 120.056,154.564 120.126,154.635 120.385,154.635 120.456,154.564 120.456,154.554 120.526,154.483 120.785,154.483 120.856,154.554 120.856,154.564 120.926,154.635 121.185,154.635 121.256,154.564 121.256,154.554 121.326,154.483 121.585,154.483 121.656,154.554 121.656,154.564 121.726,154.635 121.985,154.635 122.056,154.564 122.056,154.554 122.126,154.483 122.385,154.483 122.456,154.554 122.456,154.564 122.526,154.635 122.785,154.635 122.856,154.564 122.856,154.554 122.926,154.483 123.185,154.483 123.256,154.554 123.256,154.564 123.326,154.635 123.585,154.635 123.656,154.564 123.656,154.554 123.726,154.483 123.985,154.483 124.056,154.554 124.056,154.564 124.126,154.635 124.385,154.635 124.456,154.564 124.456,154.554 124.526,154.483 124.785,154.483 124.856,154.554 124.856,154.564 124.926,154.635 125.185,154.635 125.256,154.564 125.256,154.554 125.326,154.483 125.585,154.483 125.656,154.554 125.656,154.564 125.726,154.635 125.985,154.635 126.056,154.564 126.056,154.554 126.126,154.483 126.385,154.483 126.456,154.554 126.456,154.564 126.526,154.635 126.785,154.635 126.856,154.564 126.856,154.554 126.926,154.483 127.185,154.483 127.256,154.554 127.256,154.564 127.326,154.635 127.585,154.635 127.656,154.564 127.656,154.554 127.726,154.483 127.985,154.483 128.056,154.554 128.056,154.564 128.126,154.635 128.385,154.635 128.456,154.564 128.456,154.554 128.526,154.483 128.785,154.483 128.856,154.554 128.856,154.564 128.926,154.635 129.185,154.635 129.256,154.564 129.256,154.554 129.326,154.483 129.585,154.483 129.656,154.554 129.656,154.564 129.726,154.635 129.985,154.635 130.056,154.564 130.056,154.554 130.126,154.483 130.385,154.483 130.456,154.554 130.456,154.564 130.526,154.635 130.785,154.635 130.856,154.564 130.856,154.554 130.926,154.483 131.185,154.483 131.256,154.554 131.256,154.564 131.326,154.635 131.585,154.635 131.656,154.564 131.656,154.554 131.726,154.483 131.985,154.483 132.056,154.554 132.056,154.564 132.126,154.635 132.385,154.635 132.456,154.564 132.456,154.554 132.526,154.483 132.785,154.483 132.856,154.554 132.856,154.564 132.926,154.635 133.185,154.635 133.256,154.564 133.256,154.554 133.326,154.483 133.585,154.483 133.656,154.554 133.656,154.564 133.726,154.635 133.985,154.635 134.056,154.564 134.056,154.554 134.126,154.483 134.417,154.483 134.629,154.271 134.629,154.171 134.617,154.159 134.617,154.059 134.8,153.876 134.9,153.876 134.912,153.888 135.012,153.888 135.195,153.705 135.195,153.605 135.139,153.55 135.139,153.45 135.322,153.267 135.422,153.267 135.478,153.322 135.578,153.322 135.761,153.139 135.761,153.039 135.705,152.984 135.705,152.884 135.888,152.701 135.988,152.701 136.043,152.757 136.143,152.757 136.326,152.574 136.326,152.474 136.271,152.418 136.271,152.318 136.454,152.136 136.554,152.136 136.609,152.191 136.709,152.191 136.892,152.008 136.892,151.908 136.845,151.862 136.845,151.762 137.028,151.579 137.128,151.579 137.175,151.625 137.275,151.625 137.769,151.131 137.769,150.831 137.698,150.76 137.681,150.76 137.61,150.69 137.61,150.431 137.681,150.36 137.698,150.36 137.769,150.29 137.769,149.99 137.698,149.919 137.681,149.919 137.61,149.848 137.61,149.59 137.681,149.519 137.698,149.519 137.769,149.448 U5.33@137.769,147.425
SD_A9: U1.A7 U5.34 | length 45.4
  Top Layer w0.1: U1.A7@106.928,148.926 112.104,154.102 112.404,154.102 112.475,154.173 112.475,154.183 112.546,154.254 112.804,154.254 112.875,154.183 112.875,154.173 112.946,154.102 113.204,154.102 113.275,154.173 113.275,154.183 113.346,154.254 113.604,154.254 113.675,154.183 113.675,154.173 113.746,154.102 114.004,154.102 114.075,154.173 114.075,154.183 114.146,154.254 114.404,154.254 114.475,154.183 114.475,154.173 114.546,154.102 114.804,154.102 114.875,154.173 114.875,154.183 114.946,154.254 115.204,154.254 115.275,154.183 115.275,154.173 115.346,154.102 115.604,154.102 115.675,154.173 115.675,154.183 115.746,154.254 116.004,154.254 116.075,154.183 116.075,154.173 116.146,154.102 116.404,154.102 116.475,154.173 116.475,154.183 116.546,154.254 116.804,154.254 116.875,154.183 116.875,154.173 116.946,154.102 117.204,154.102 117.275,154.173 117.275,154.183 117.346,154.254 117.604,154.254 117.675,154.183 117.675,154.173 117.746,154.102 118.004,154.102 118.075,154.173 118.075,154.183 118.146,154.254 118.404,154.254 118.475,154.183 118.475,154.173 118.546,154.102 118.804,154.102 118.875,154.173 118.875,154.183 118.946,154.254 119.204,154.254 119.275,154.183 119.275,154.173 119.346,154.102 119.604,154.102 119.675,154.173 119.675,154.183 119.746,154.254 120.004,154.254 120.075,154.183 120.075,154.173 120.146,154.102 120.404,154.102 120.475,154.173 120.475,154.183 120.546,154.254 120.804,154.254 120.875,154.183 120.875,154.173 120.946,154.102 121.204,154.102 121.275,154.173 121.275,154.183 121.346,154.254 121.604,154.254 121.675,154.183 121.675,154.173 121.746,154.102 122.004,154.102 122.075,154.173 122.075,154.183 122.146,154.254 122.404,154.254 122.475,154.183 122.475,154.173 122.546,154.102 122.804,154.102 122.875,154.173 122.875,154.183 122.946,154.254 123.204,154.254 123.275,154.183 123.275,154.173 123.346,154.102 123.604,154.102 123.675,154.173 123.675,154.183 123.746,154.254 124.004,154.254 124.075,154.183 124.075,154.173 124.146,154.102 124.404,154.102 124.475,154.173 124.475,154.183 124.546,154.254 124.804,154.254 124.875,154.183 124.875,154.173 124.946,154.102 125.204,154.102 125.275,154.173 125.275,154.183 125.346,154.254 125.604,154.254 125.675,154.183 125.675,154.173 125.746,154.102 126.004,154.102 126.075,154.173 126.075,154.183 126.146,154.254 126.404,154.254 126.475,154.183 126.475,154.173 126.546,154.102 126.804,154.102 126.875,154.173 126.875,154.183 126.946,154.254 127.204,154.254 127.275,154.183 127.275,154.173 127.346,154.102 127.604,154.102 127.675,154.173 127.675,154.183 127.746,154.254 128.004,154.254 128.075,154.183 128.075,154.173 128.146,154.102 128.404,154.102 128.475,154.173 128.475,154.183 128.546,154.254 128.804,154.254 128.875,154.183 128.875,154.173 128.946,154.102 129.204,154.102 129.275,154.173 129.275,154.183 129.346,154.254 129.604,154.254 129.675,154.183 129.675,154.173 129.746,154.102 130.004,154.102 130.075,154.173 130.075,154.183 130.146,154.254 130.404,154.254 130.475,154.183 130.475,154.173 130.546,154.102 130.804,154.102 130.875,154.173 130.875,154.183 130.946,154.254 131.204,154.254 131.275,154.183 131.275,154.173 131.346,154.102 131.604,154.102 131.675,154.173 131.675,154.183 131.746,154.254 132.004,154.254 132.075,154.183 132.075,154.173 132.146,154.102 132.404,154.102 132.475,154.173 132.475,154.183 132.546,154.254 132.804,154.254 132.875,154.183 132.875,154.173 132.946,154.102 133.204,154.102 133.275,154.173 133.275,154.183 133.346,154.254 133.604,154.254 133.675,154.183 133.675,154.173 133.746,154.102 134.163,154.102 134.375,153.89 134.375,153.79 134.363,153.778 134.363,153.678 134.546,153.495 134.646,153.495 134.658,153.507 134.758,153.507 134.941,153.324 134.941,153.224 134.885,153.169 134.885,153.069 135.068,152.886 135.168,152.886 135.224,152.941 135.324,152.941 135.507,152.758 135.507,152.658 135.451,152.603 135.451,152.503 135.634,152.32 135.734,152.32 135.789,152.376 135.889,152.376 136.072,152.193 136.072,152.093 136.017,152.037 136.017,151.937 136.2,151.755 136.3,151.755 136.355,151.81 136.455,151.81 136.969,151.296 136.969,151.288 136.898,151.217 136.52,151.217 136.449,151.147 136.449,150.888 136.52,150.817 136.898,150.817 136.969,150.747 136.969,150.488 136.898,150.417 136.52,150.417 136.449,150.347 136.449,150.088 136.52,150.017 136.898,150.017 136.969,149.947 136.969,149.688 136.898,149.617 136.52,149.617 136.449,149.547 136.449,149.288 136.52,149.217 136.898,149.217 136.969,149.147 136.969,148.888 136.898,148.817 136.52,148.817 136.449,148.747 136.449,148.488 136.52,148.417 136.898,148.417 136.969,148.347 U5.34@136.969,147.425
SD_A10: U1.T7 U5.22 | length 45.1
  Top Layer w0.1: U1.T7@106.928,136.926 112.739,131.115 117.5,131.115 117.57,131.044 117.57,130.932 117.641,130.861 117.9,130.861 117.97,130.932 117.97,131.044 118.041,131.115 118.3,131.115 118.37,131.044 118.37,130.932 118.441,130.861 118.7,130.861 118.77,130.932 118.77,131.044 118.841,131.115 119.1,131.115 119.17,131.044 119.17,130.932 119.241,130.861 119.5,130.861 119.57,130.932 119.57,131.044 119.641,131.115 119.9,131.115 119.97,131.044 119.97,130.932 120.041,130.861 120.3,130.861 120.37,130.932 120.37,131.044 120.441,131.115 120.7,131.115 120.77,131.044 120.77,130.932 120.841,130.861 121.1,130.861 121.17,130.932 121.17,131.044 121.241,131.115 121.5,131.115 121.57,131.044 121.57,130.932 121.641,130.861 121.9,130.861 121.97,130.932 121.97,131.044 122.041,131.115 122.3,131.115 122.37,131.044 122.37,130.932 122.441,130.861 122.7,130.861 122.77,130.932 122.77,131.044 122.841,131.115 123.1,131.115 123.17,131.044 123.17,130.932 123.241,130.861 123.5,130.861 123.57,130.932 123.57,131.044 123.641,131.115 123.9,131.115 123.97,131.044 123.97,130.932 124.041,130.861 124.3,130.861 124.37,130.932 124.37,131.044 124.441,131.115 124.7,131.115 124.77,131.044 124.77,130.932 124.841,130.861 125.1,130.861 125.17,130.932 125.17,131.044 125.241,131.115 125.5,131.115 125.57,131.044 125.57,130.932 125.641,130.861 125.9,130.861 125.97,130.932 125.97,131.044 126.041,131.115 126.3,131.115 126.37,131.044 126.37,130.932 126.441,130.861 126.7,130.861 126.77,130.932 126.77,131.044 126.841,131.115 127.1,131.115 127.17,131.044 127.17,130.932 127.241,130.861 127.5,130.861 127.57,130.932 127.57,131.044 127.641,131.115 127.9,131.115 127.97,131.044 127.97,130.932 128.041,130.861 128.3,130.861 128.37,130.932 128.37,131.044 128.441,131.115 128.7,131.115 128.77,131.044 128.77,130.932 128.841,130.861 129.1,130.861 129.17,130.932 129.17,131.044 129.241,131.115 129.5,131.115 129.57,131.044 129.57,130.932 129.641,130.861 129.9,130.861 129.97,130.932 129.97,131.044 130.041,131.115 130.3,131.115 130.37,131.044 130.37,130.932 130.441,130.861 130.7,130.861 130.77,130.932 130.77,131.044 130.841,131.115 131.1,131.115 131.17,131.044 131.17,130.932 131.241,130.861 131.5,130.861 131.57,130.932 131.57,131.044 131.641,131.115 131.9,131.115 131.97,131.044 131.97,130.932 132.041,130.861 132.3,130.861 132.37,130.932 132.37,131.044 132.441,131.115 132.7,131.115 132.77,131.044 132.77,130.932 132.841,130.861 133.1,130.861 133.17,130.932 133.17,131.044 133.241,131.115 133.5,131.115 133.57,131.044 133.57,130.932 133.641,130.861 133.9,130.861 133.97,130.932 133.97,131.044 134.041,131.115 134.3,131.115 134.37,131.044 134.37,130.932 134.441,130.861 134.7,130.861 134.77,130.932 134.77,131.044 134.841,131.115 135.1,131.115 135.17,131.044 135.17,130.932 135.241,130.861 135.5,130.861 135.57,130.932 135.57,131.044 135.641,131.115 135.941,131.115 137.769,132.943 U5.22@137.769,136.141
SD_A11: U1.A8 U5.35 | length 44.2
  Top Layer w0.1: U1.A8@107.728,148.926 112.396,153.594 112.696,153.594 112.767,153.665 112.767,153.777 112.837,153.848 113.096,153.848 113.167,153.777 113.167,153.665 113.237,153.594 113.496,153.594 113.567,153.665 113.567,153.777 113.637,153.848 113.896,153.848 113.967,153.777 113.967,153.665 114.037,153.594 114.296,153.594 114.367,153.665 114.367,153.777 114.437,153.848 114.696,153.848 114.767,153.777 114.767,153.665 114.837,153.594 115.096,153.594 115.167,153.665 115.167,153.777 115.237,153.848 115.496,153.848 115.567,153.777 115.567,153.665 115.637,153.594 115.896,153.594 115.967,153.665 115.967,153.777 116.037,153.848 116.296,153.848 116.367,153.777 116.367,153.665 116.437,153.594 116.696,153.594 116.767,153.665 116.767,153.777 116.837,153.848 117.096,153.848 117.167,153.777 117.167,153.665 117.237,153.594 117.496,153.594 117.567,153.665 117.567,153.777 117.637,153.848 117.896,153.848 117.967,153.777 117.967,153.665 118.037,153.594 118.296,153.594 118.367,153.665 118.367,153.777 118.437,153.848 118.696,153.848 118.767,153.777 118.767,153.665 118.837,153.594 119.096,153.594 119.167,153.665 119.167,153.777 119.237,153.848 119.496,153.848 119.567,153.777 119.567,153.665 119.637,153.594 119.896,153.594 119.967,153.665 119.967,153.777 120.037,153.848 120.296,153.848 120.367,153.777 120.367,153.665 120.437,153.594 120.696,153.594 120.767,153.665 120.767,153.777 120.837,153.848 121.096,153.848 121.167,153.777 121.167,153.665 121.237,153.594 121.496,153.594 121.567,153.665 121.567,153.777 121.637,153.848 121.896,153.848 121.967,153.777 121.967,153.665 122.037,153.594 122.296,153.594 122.367,153.665 122.367,153.777 122.437,153.848 122.696,153.848 122.767,153.777 122.767,153.665 122.837,153.594 123.096,153.594 123.167,153.665 123.167,153.777 123.237,153.848 123.496,153.848 123.567,153.777 123.567,153.665 123.637,153.594 123.896,153.594 123.967,153.665 123.967,153.777 124.037,153.848 124.296,153.848 124.367,153.777 124.367,153.665 124.437,153.594 124.696,153.594 124.767,153.665 124.767,153.777 124.837,153.848 125.096,153.848 125.167,153.777 125.167,153.665 125.237,153.594 125.496,153.594 125.567,153.665 125.567,153.777 125.637,153.848 125.896,153.848 125.967,153.777 125.967,153.665 126.037,153.594 126.296,153.594 126.367,153.665 126.367,153.777 126.437,153.848 126.696,153.848 126.767,153.777 126.767,153.665 126.837,153.594 127.096,153.594 127.167,153.665 127.167,153.777 127.237,153.848 127.496,153.848 127.567,153.777 127.567,153.665 127.637,153.594 127.896,153.594 127.967,153.665 127.967,153.777 128.037,153.848 128.296,153.848 128.367,153.777 128.367,153.665 128.437,153.594 128.696,153.594 128.767,153.665 128.767,153.777 128.837,153.848 129.096,153.848 129.167,153.777 129.167,153.665 129.237,153.594 129.496,153.594 129.567,153.665 129.567,153.777 129.637,153.848 129.896,153.848 129.967,153.777 129.967,153.665 130.037,153.594 130.296,153.594 130.367,153.665 130.367,153.777 130.437,153.848 130.696,153.848 130.767,153.777 130.767,153.665 130.837,153.594 131.096,153.594 131.167,153.665 131.167,153.777 131.237,153.848 131.496,153.848 131.567,153.777 131.567,153.665 131.637,153.594 131.896,153.594 131.967,153.665 131.967,153.777 132.037,153.848 132.296,153.848 132.367,153.777 132.367,153.665 132.437,153.594 132.696,153.594 132.767,153.665 132.767,153.777 132.837,153.848 133.096,153.848 133.167,153.777 133.167,153.665 133.237,153.594 134.036,153.594 136.169,151.461 U5.35@136.169,147.425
